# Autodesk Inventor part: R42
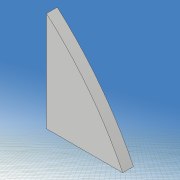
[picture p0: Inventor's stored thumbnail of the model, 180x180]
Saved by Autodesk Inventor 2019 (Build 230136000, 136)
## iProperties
Created: 2021-05
Part Number: R42
Material: 一般
Document SubType Name: Modeling
Designer: kikut
Density: 1 g/cm^3
Appearance: 既定
Mass: 0.0338306 g
Surface Area: 1.31176 cm^2
Volume: 0.0338306 cm^3
Author: kikut
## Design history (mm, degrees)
sketch "スケッチ1"
  geometry: L1 (80, 60)-(-80, 60); L2 (-80, 60)-(-80, -60); L3 (-80, -60)-(80, -60); L4 (80, -60)-(80, 60); L5 (80, 60)-(-80, -60); L6 (-80, 60)-(80, -60); 1 further point
  constraints: 12 end point, 2 midpoint, 2 parallel, 1 horizontal, 1 perpendicular
  dimensions: "d0" = 160 distance of L2.end L3.end; "d1" = 120 distance of L1.end L2.end
extrude "押し出し1" new body sketch "スケッチ1" stored distance "d2" = 0.6; taper "d3" = 0 deg
sketch "スケッチ2"
  geometry: L1 (-140, 0)-(140, 0) reference; L2 (0, -54)-(20, -30); L3 (0, 54)-(20, 30); L4 (0, -3)-(6.514, -3); L5 (6.514, -3)-(16, -6); L6 (16, -6)-(24, -3); L7 (24, -3)-(33.716, -3); L8 (0, 3)-(6.514, 3); L9 (6.514, 3)-(16, 6); L10 (16, 6)-(24, 3); L11 (24, 3)-(33.716, 3); L12 (0, -98)-(0, 98) reference; L13 (-100, -70)-(100, -70); L14 (100, -70)-(100, 70); L15 (100, 70)-(-100, 70); L16 (-100, 70)-(-100, -70); L17 (-100, -70)-(100, 70); L18 (100, -70)-(-100, 70); A1 r 60 centre (54.312, 28.5) between (0, 54) and (0, 3); A2 r 60 centre (54.312, -28.5) between (0, -3) and (0, -54); A3 r 18.111 centre (18, -12) between (20, -30) and (33.716, -3); A4 r 18.111 centre (18, 12) between (33.716, 3) and (20, 30); 1 further point
  constraints: 32 end point, 8 point on circle, 8 symmetric about line, 4 centre point, 3 horizontal, 2 collinear, 2 midpoint, 2 parallel, 1 perpendicular
  dimensions: "d5" = 60 radius of A1; "d6" = 6 distance of L8.start L4.start; "d7" = 108 distance of L3.start L2.start; "d8" = 0 horizontal distance of L3.start L8.start; "d9" = 60 distance of L3.end L2.end; "d10" = 0 horizontal distance of point (0, 0) L3.start; "d11" = 20 horizontal distance of L3.start L3.end; "d12" = 24 distance of A4.centre A3.centre; "d13" = 6 distance of L11.end L7.end; "d14" = 12 distance of L9.end L5.end; "d15" = 16 distance from line of L12 L5.end; "d16" = 24 distance from line of L6.end L12; "d17" = 200 distance of L14.end L15.end; "d18" = 140 distance of L15.end L13.start; "d30" = 18 distance from line of L12 A4.centre
extrude "押し出し2" cut sketch "スケッチ2" stored distance "d19" = 10; taper "d20" = 0 deg
sketch "スケッチ3"
  geometry: L1 (49.705, -17.97)-(33.948, -15.191); L2 (33.948, -15.191)-(34.295, -13.222); L3 (34.295, -13.222)-(50.052, -16); L4 (50.052, -16)-(49.705, -17.97); L5 (49.705, -17.97)-(34.295, -13.222); L6 (33.948, -15.191)-(50.052, -16); L7 (50.052, 16)-(34.295, 13.222); L8 (34.295, 13.222)-(33.948, 15.191); L9 (33.948, 15.191)-(49.705, 17.97); L10 (49.705, 17.97)-(50.052, 16); L11 (50.052, 16)-(33.948, 15.191); L12 (34.295, 13.222)-(49.705, 17.97); L13 (-112, 0)-(112, 0) reference; L14 (0, -84)-(0, 84) reference; 3 further points
  constraints: 24 end point, 4 midpoint, 4 parallel, 2 perpendicular, 2 symmetric about line
  dimensions: "d21" = 2 distance of L3.end L1.start; "d22" = 2 distance of L9.end L7.start; "d23" = 16 distance of L8.end L9.end; "d24" = 42 distance from line of L14 point (42, 15.596); "d26" = 10 deg angle of L7 L13; "d62" = 16 distance from line of L3.end L13
extrude "押し出し3" join sketch "スケッチ3" distance "d27" = 0.6; taper "d28" = 0 deg
fillet "フィレット1" dims "d31" = 2
fillet "フィレット2" dims "d32" = 1
sketch "スケッチ6"
  geometry: L1 (-20, 60)-(80, 60); L2 (80, 60)-(80, -60); L3 (80, -60)-(-20, -60); L4 (-20, -60)-(-20, 60); L5 (-46.168, 0)-(93.832, 0) reference; L6 (0, -84)-(0, 84) reference; L7 (30, 20)-(36, 20); L8 (36, 20)-(36, 30); L9 (36, 30)-(30, 30); L10 (30, 30)-(30, 20); 1 further point
  constraints: 16 end point, 4 parallel, 2 horizontal, 2 perpendicular, 1 other
  dimensions: "d63" = 120 distance of L3.end L1.start; "d64" = 100 distance of L1.start L1.end; "d65" = 20 distance between parallel lines of L6 L4; "d66" = 6 distance of L8.end L9.end; "d73" = 10 distance of L9.end L7.start; "d74" = 20 distance between parallel lines of L7 L5; "d75" = 50 distance between parallel lines of L10 L4
extrude "押し出し4" cut sketch "スケッチ6" stored distance "d70" = 10; taper "d71" = 0 deg
node "ソリッド1"
